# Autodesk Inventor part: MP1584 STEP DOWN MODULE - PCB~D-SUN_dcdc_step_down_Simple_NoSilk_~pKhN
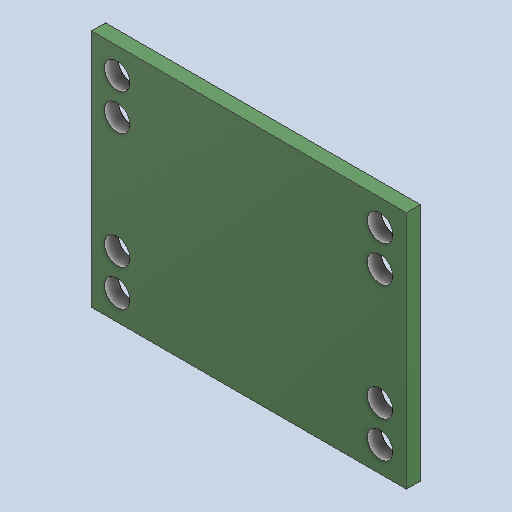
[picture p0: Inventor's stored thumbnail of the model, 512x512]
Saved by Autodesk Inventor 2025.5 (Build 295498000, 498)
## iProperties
Created: 2026-10
Part Number: MP1584 STEP DOWN MODULE - PCB~D-SUN_dcdc_step_down_Simple_NoSilk_~pKhN
Material: Genérico
Document SubType Name: Modeling
Designer: Luis M
Density: 1 g/cm^3
Appearance: Valor por defecto
Author: Luis M
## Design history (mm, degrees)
feature "Base1"
node "Sólido1"
